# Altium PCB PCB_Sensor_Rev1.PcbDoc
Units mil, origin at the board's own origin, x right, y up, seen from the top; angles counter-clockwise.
Board outline 1760.04 x 1230.03 mil, 4 copper layers (Top Layer, Layer 1 (GND), Layer 2 (PWR), Bottom Layer), stack 61.456 mil thick; 69 components, 58 nets, 289 pads, 108 vias.
Unrouted connection lines stored in the file: 3.
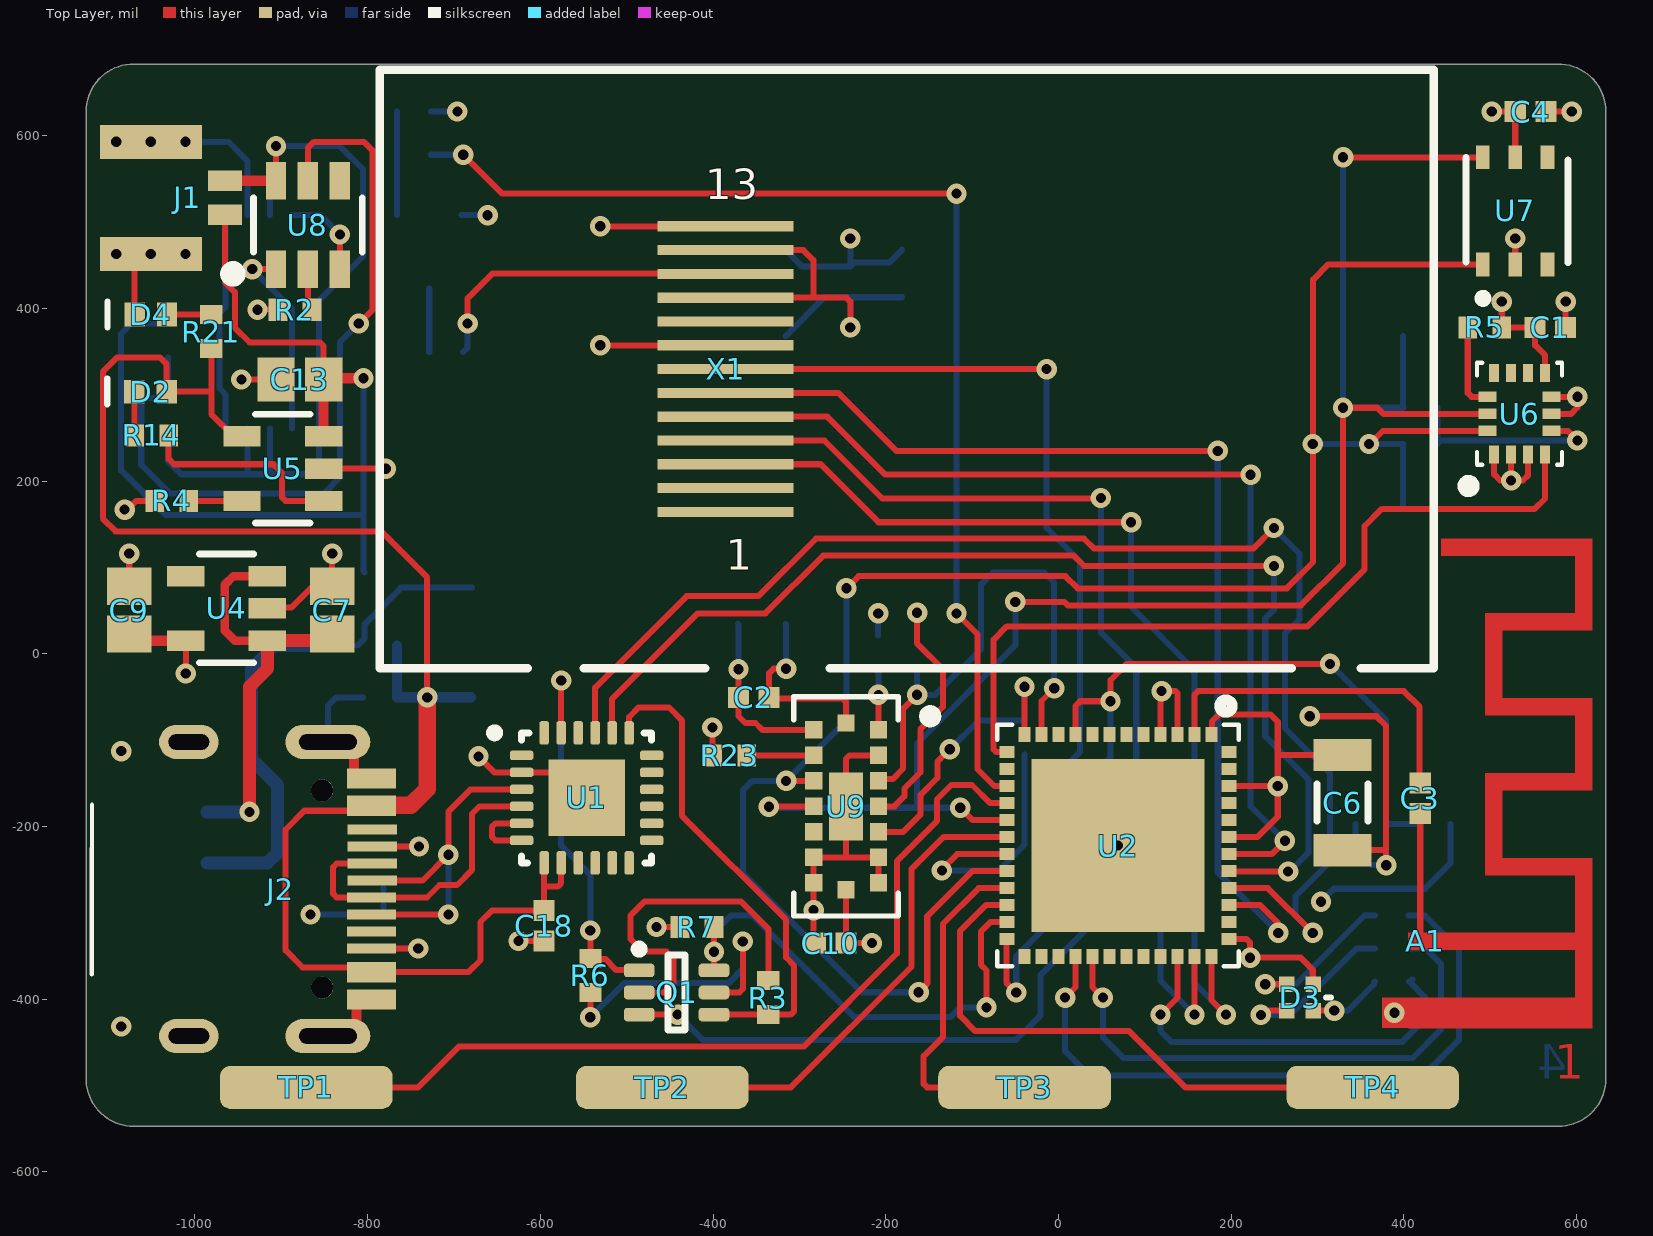
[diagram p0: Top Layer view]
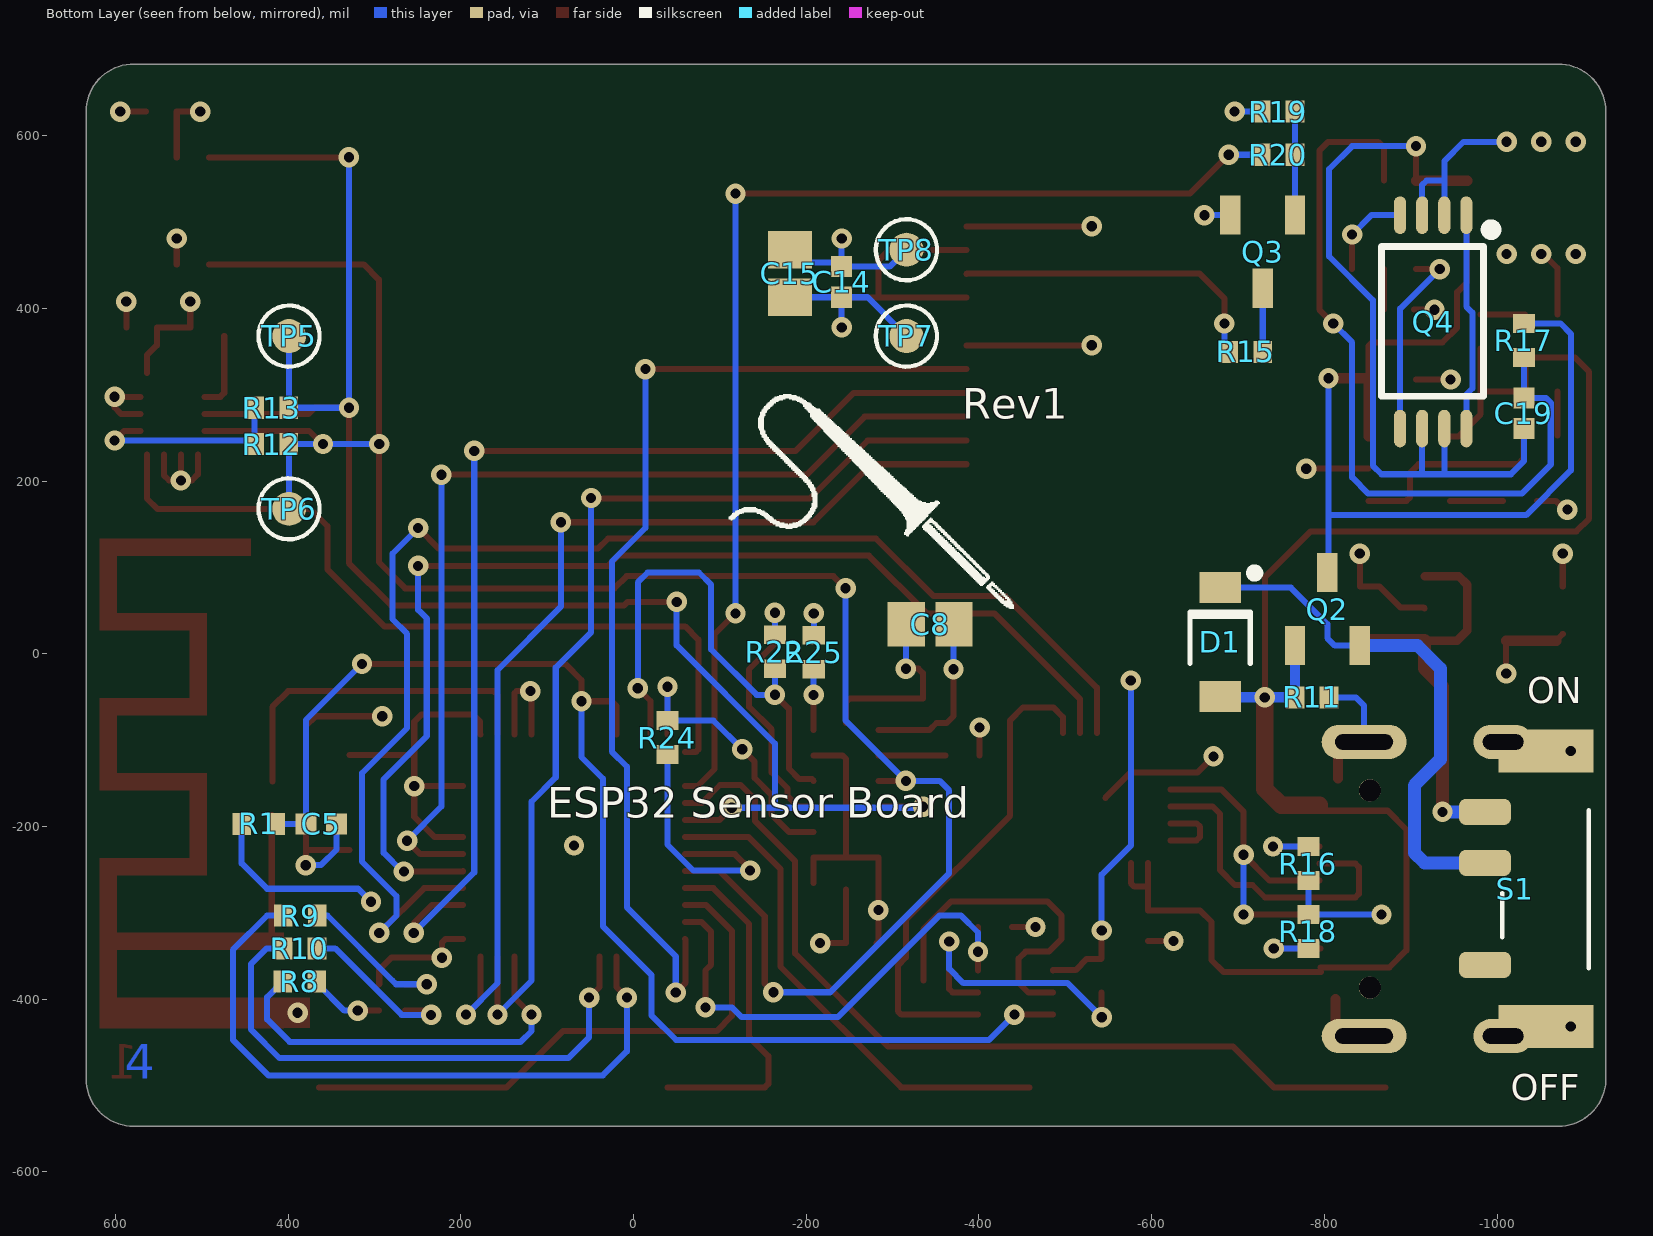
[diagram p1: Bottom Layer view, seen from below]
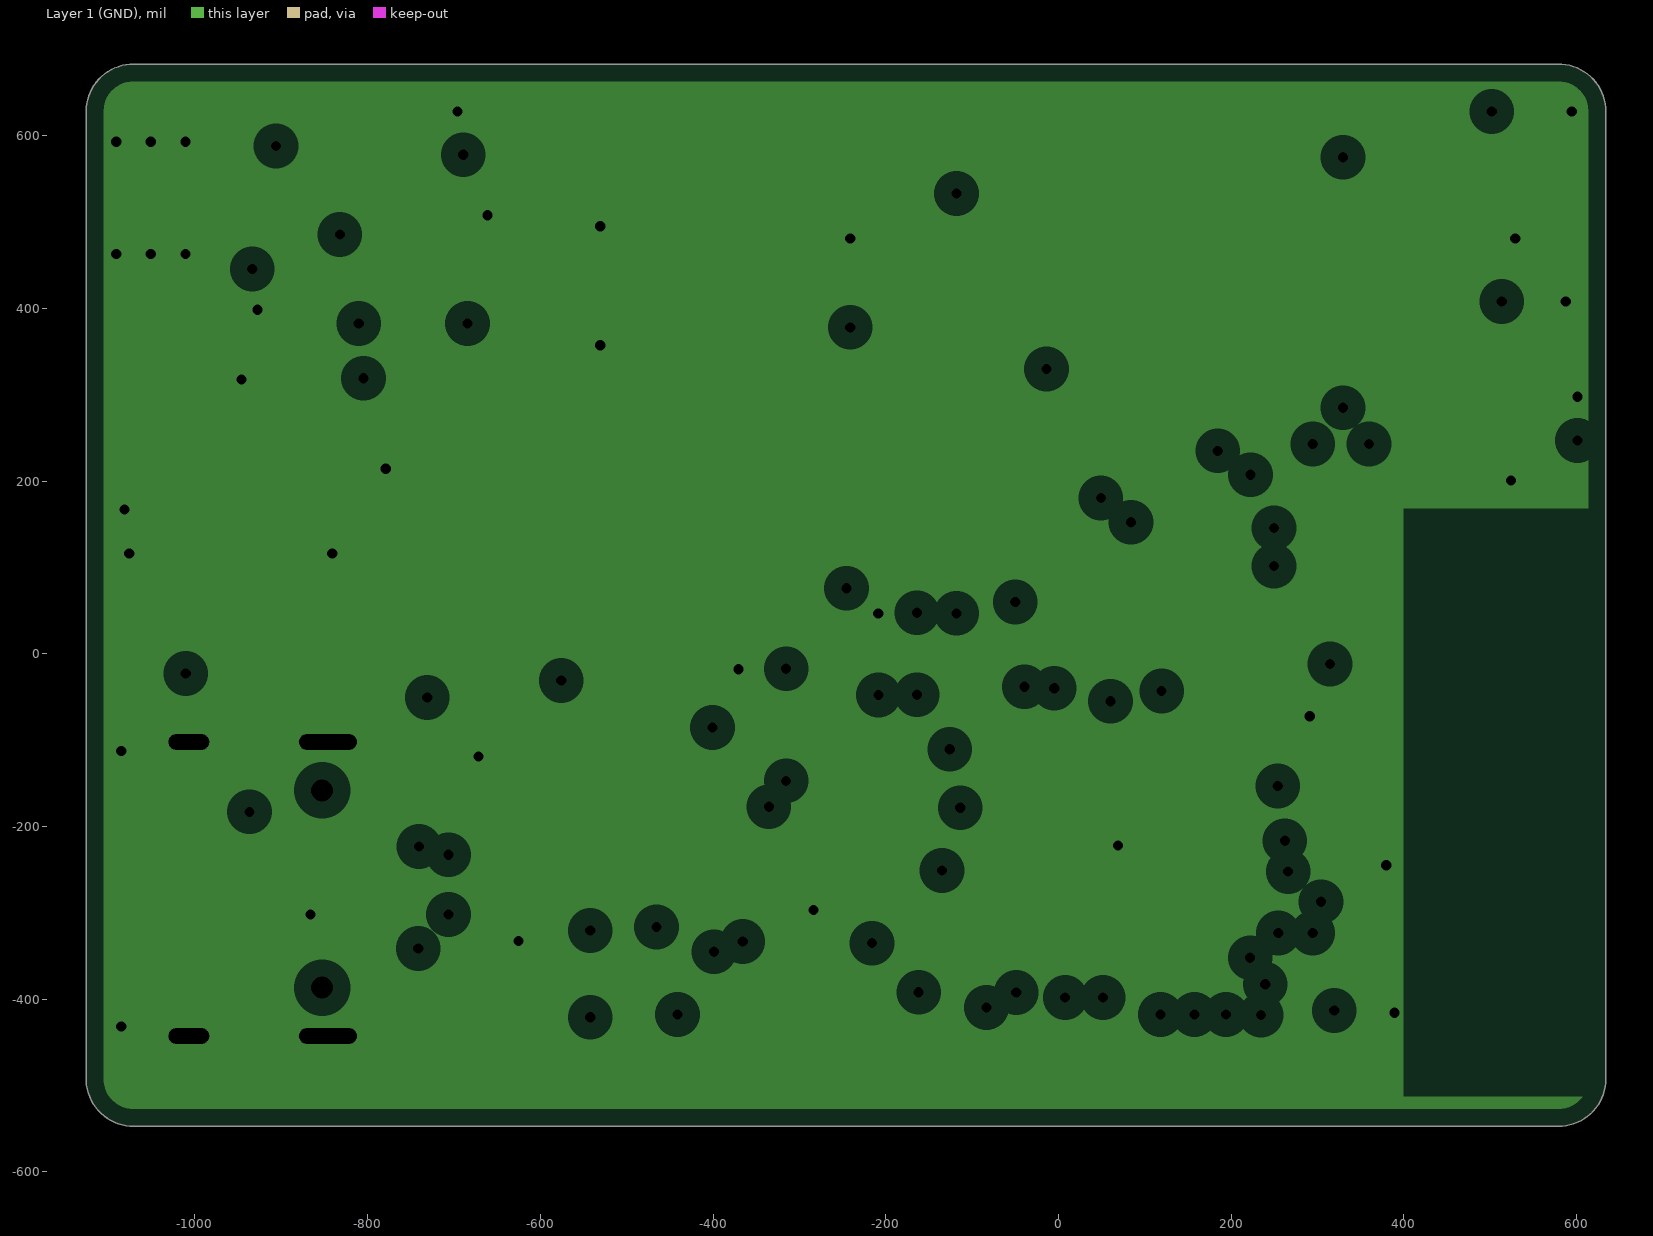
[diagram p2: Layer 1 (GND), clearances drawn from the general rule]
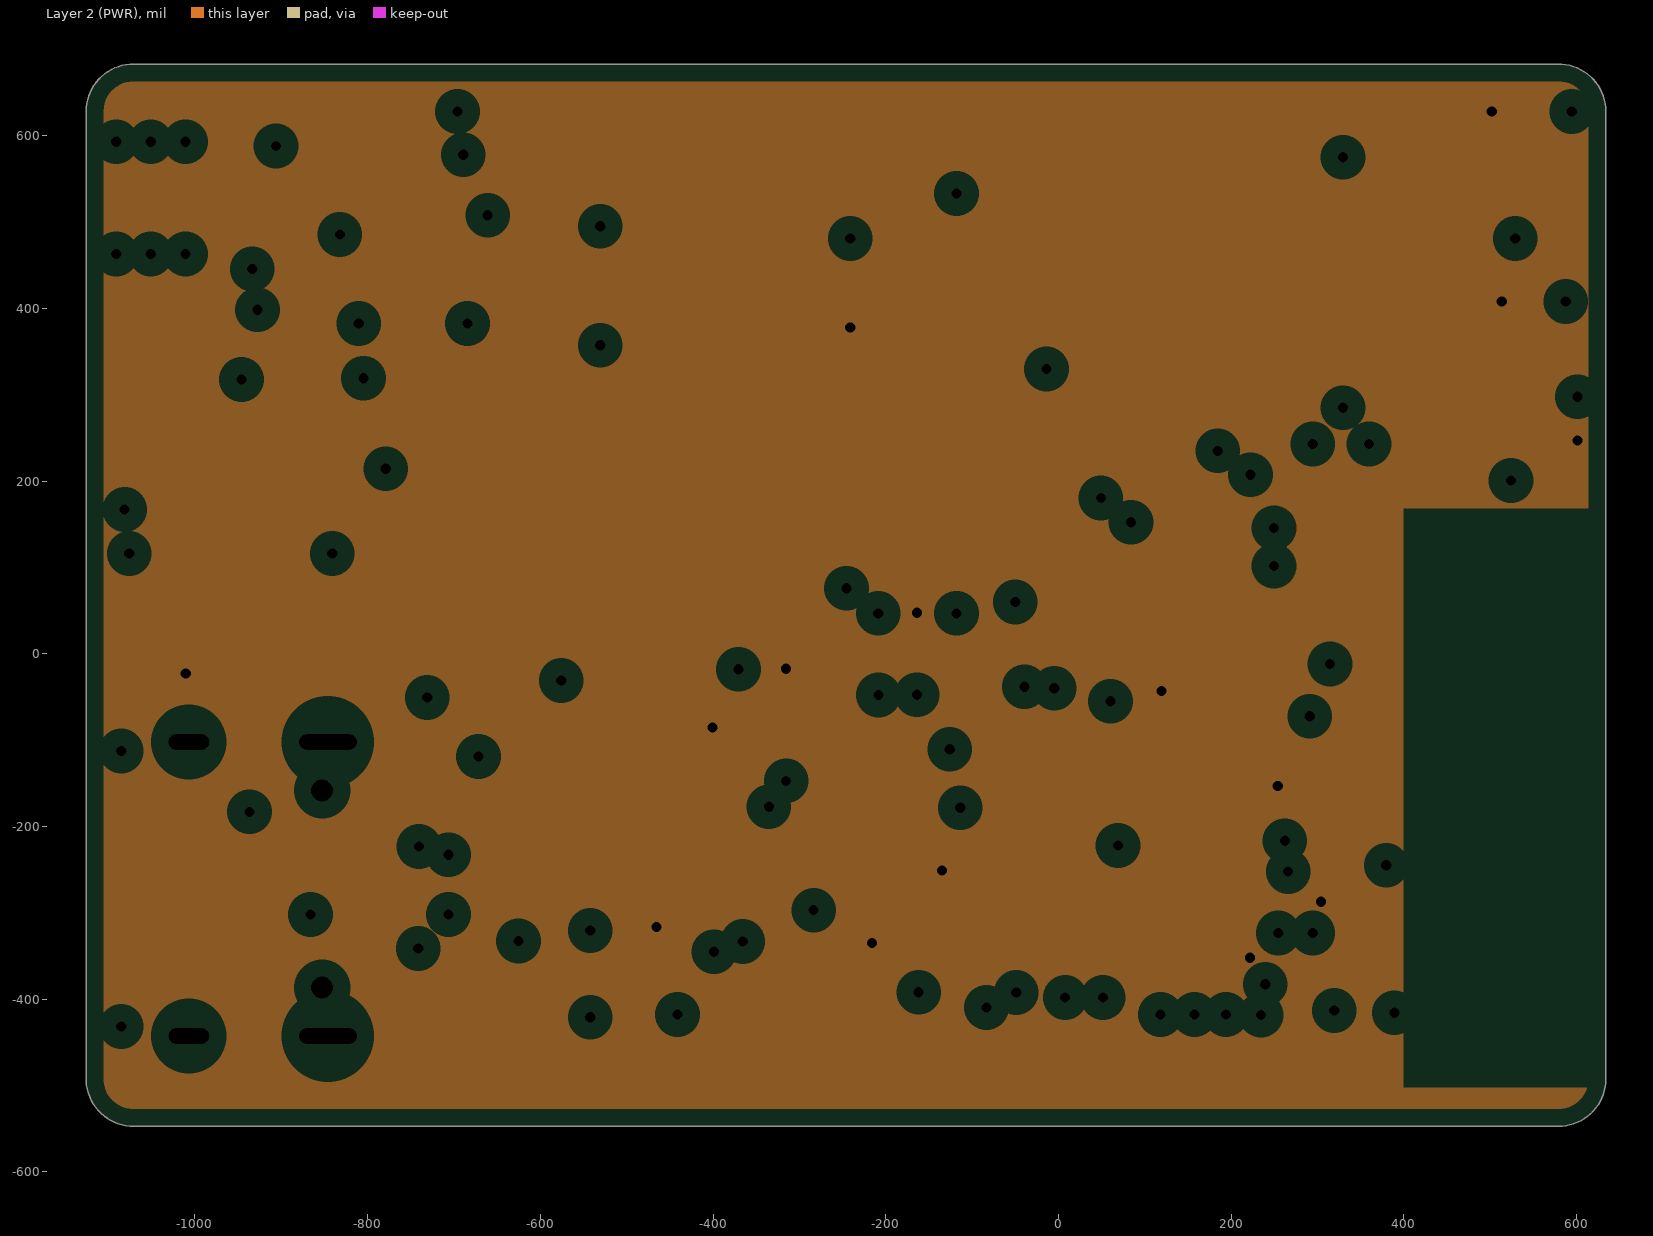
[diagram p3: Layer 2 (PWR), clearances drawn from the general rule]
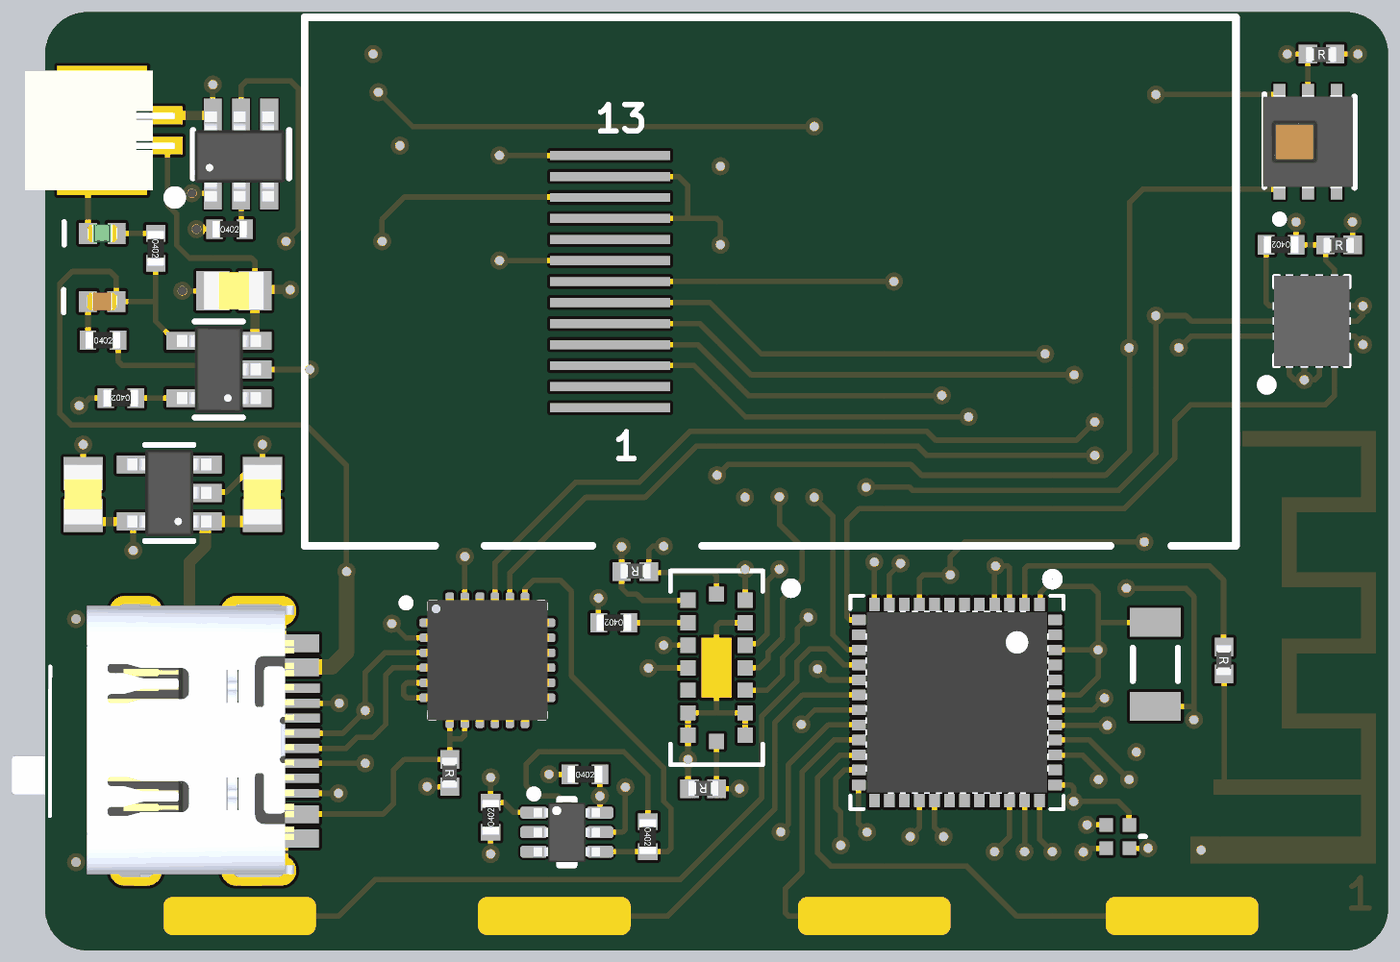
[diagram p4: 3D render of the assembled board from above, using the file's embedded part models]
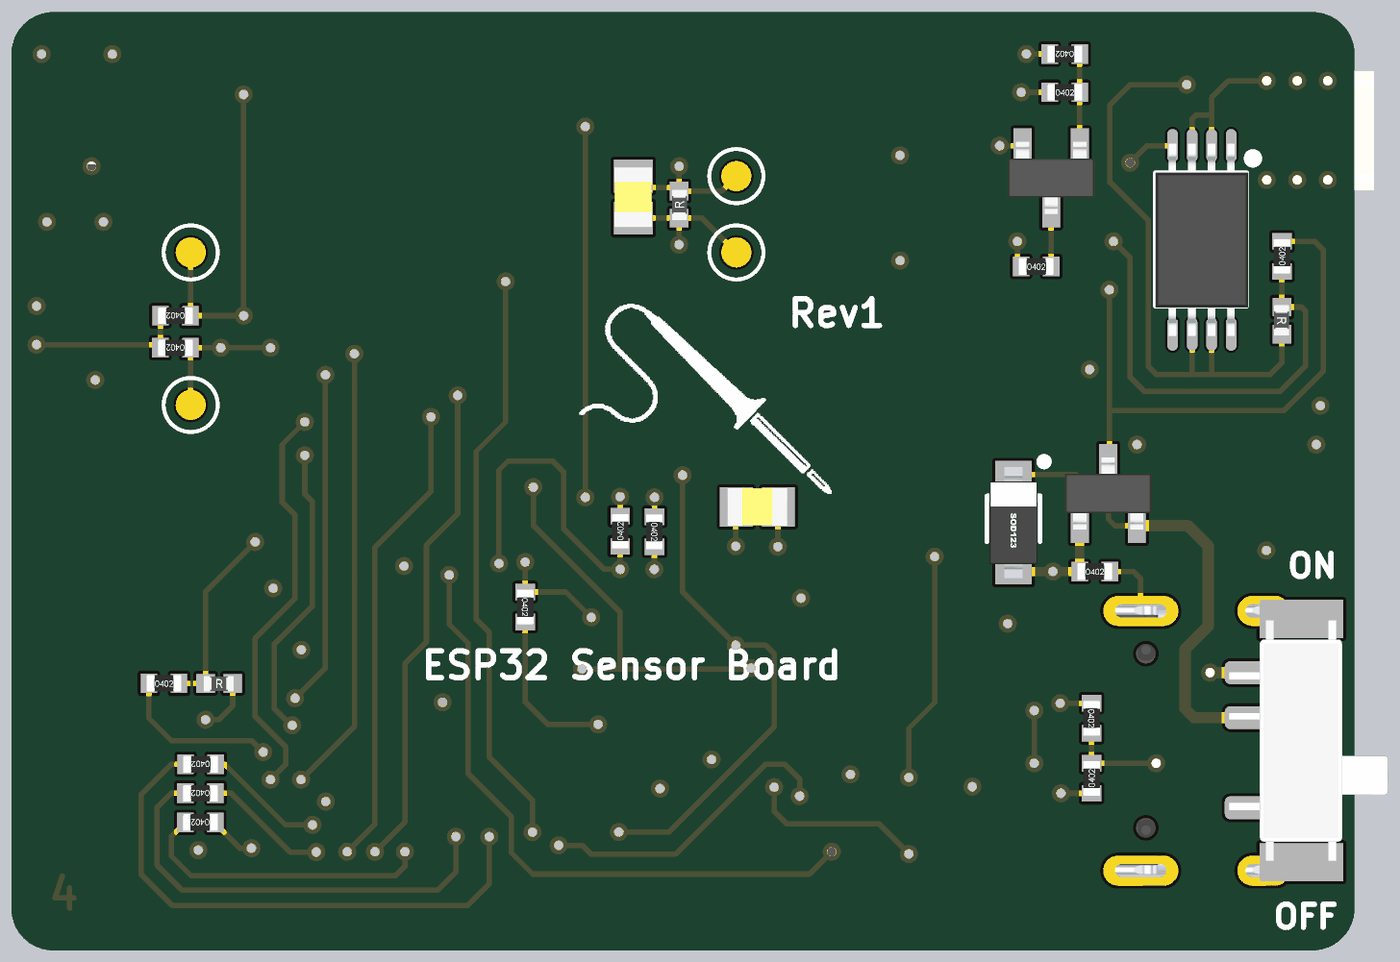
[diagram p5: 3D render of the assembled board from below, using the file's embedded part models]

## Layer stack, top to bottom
Top Solder: solder mask 0.4, Solder Resist, Dk 3.5
Top Layer: signal copper 1.4
Dielectric 2: prepreg 2.8, PP-006, Dk 4.1
Layer 1 (GND): plane copper 1.378, net GND
Dielectric 1: dielectric 50.3, FR-4, Dk 4.8
Layer 2 (PWR): plane copper 1.378, net +3.3V
Dielectric 3: prepreg 2.8, PP-006, Dk 4.1
Bottom Layer: signal copper 1.4
Bottom Solder: solder mask 0.4, Solder Resist, Dk 3.5

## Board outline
-1126.1,-497.17 -1126.1,-493.37 cw(c-1071.1,-492.17) -1126.12,-492.17 cw(c-1121.1,-492.17) -1126.1,-491.81 -1126.12,627.83 cw(c-1121.1,627.83) -1126.12,627.98 cw(c-1071.1,627.83) -1070.79,682.85 cw(c-1070.6,677.84) -1070.6,682.85 578.23,682.85 cw(c578.39,677.84) 578.34,682.85 cw(c578.89,627.84) 633.91,627.84 cw(c628.89,627.84) 633.9,627.7 633.92,-492.17 cw(c628.9,-492.17) 633.92,-492.17 cw(c628.9,-492.17) 633.92,-492.32 cw(c578.9,-492.17) 578.52,-547.18 cw(c578.4,-542.17) 578.4,-547.18 -1070.58,-547.18 ccw(c-1071.1,-492.17) -1070.55,-547.18 -1070.58,-547.18 cw(c-1071.1,-492.17) -1125.66,-499.23 cw(c-1121.09,-497.17)

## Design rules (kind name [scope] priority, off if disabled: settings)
Clearance Clearance_1 [All vs InComponent('U9')] p1: gap=5 ignorepadtopadclearanceinfootprint=FALSE
Clearance Clearance_J2 [InComponent('J2')] p2: gap=5 ignorepadtopadclearanceinfootprint=FALSE
Clearance Clearance_Q4 [InComponent('Q4')] p3: gap=9.2 ignorepadtopadclearanceinfootprint=FALSE
Clearance Clearance_U7 [All vs InComponent('U7')] p4: gap=7 ignorepadtopadclearanceinfootprint=FALSE
Clearance Clearance_H1 [All vs InComponent('H1')] p5: gap=9.5 ignorepadtopadclearanceinfootprint=FALSE
Clearance Clearance_U3 [All vs InComponent('U3')] p6: gap=9.5 ignorepadtopadclearanceinfootprint=FALSE
Clearance Clearance_Q1 [All vs InComponent('Q1')] p7: gap=9.5 ignorepadtopadclearanceinfootprint=FALSE
Clearance Clearance_X1 [All vs InComponent('X1')] p8: gap=8.5 ignorepadtopadclearanceinfootprint=FALSE
Clearance Clearance_U2 [All vs InComponent('U2')] p9: gap=5.8 ignorepadtopadclearanceinfootprint=FALSE
Clearance Clearance_U1 [All vs InComponent('U1')] p10: gap=7.8 ignorepadtopadclearanceinfootprint=FALSE
Clearance Clearance_U6 [All vs InComponent('U6')] p11: gap=7.5 ignorepadtopadclearanceinfootprint=FALSE
Clearance [All] p12: gap=10 ignorepadtopadclearanceinfootprint=FALSE except(0: Arc-Hole Track-Hole SMDPad-Hole THPad-Hole Via-Hole Fill-Hole Poly-Hole Region-Hole Text-Hole)
HoleSize [All] p1: absolutevalues=TRUE maxlimit=200 minlimit=1 maxpercent=80.000 minpercent=20.000
MinimumSolderMaskSliver MinimumSolderMaskSliver_U1 [All vs InComponent('U1')] p1: minsoldermaskwidth=0.5
MinimumSolderMaskSliver MinimumSolderMaskSliver_X1 [All vs InComponent('X1')] p2: minsoldermaskwidth=0.6
MinimumSolderMaskSliver [All] p3: minsoldermaskwidth=1
PlaneClearance [All] p1: clearance=20
PlaneConnect [All] p1: planeconnectstyle=Direct reliefexpansion=20 reliefentries=4 reliefconductorwidth=10 reliefairgap=10
PolygonConnect [All] p1: connectstyle=Relief reliefconductorwidth=10 reliefentries=4 polygonreliefangle="90 Angle" airgapwidth=10
RoutingVias [All] p1: holewidth=11.81 width=23.62 viastyle="Through Hole" minholewidth=11.81 minwidth=23.62 maxholewidth=11.81 maxwidth=23.62
SilkToSilkClearance [All] p1: silktosilkclearance=5
SilkToSolderMaskClearance [IsPad] p1: minsilkscreentomaskgap=5 clearancetoexposedcopper=TRUE
SolderMaskExpansion [All] p1: expansion=4 istentingtop=FALSE
Width [All] p1: maxlimit=40 minlimit=7 preferedwidth=7
24 further rules are at their usual default settings.

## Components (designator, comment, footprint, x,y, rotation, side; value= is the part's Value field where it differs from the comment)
A1 "Antenna_PCB" "ANTENNA PCB" 424.91,-333.17 r0 top locked value="PCB Antenna"
C1 "0.1uF" CAPC1005X56N 569.57,377.83 r0 top
C2 "0.1uF" CAPC1005X56N -352.83,-50.55 r180 top
C3 "1.5pF" CAPC1005X56N 418.91,-167.17 r270 top
C4 "0.1uF" CAPC1005X56N 546.61,627.84 r0 top
C5 "0.1uF" CAPC1005X56N 361.62,-197.17 r180 bottom
C6 "100uF" CAPC3216X160L 328.91,-172.28 r270 top
C7 "10uF" CAPC2012X140N -841.1,50.39 r90 top
C8 "4.7uF" CAPC2012X140N -343.65,34.2 r180 bottom
C9 "10uF" CAPC2012X140N -1076.1,50.39 r90 top
C10 "0.1uF" CAPC1005X56N -263.81,-335.13 r180 top
C13 "10uF" CAPC2012X140N -878.66,317.6 r180 top
C14 "0.1uF" CAPC1005X56N -241.1,430.55 r90 bottom
C15 "10uF" CAPC2012X140N -181.1,440.39 r90 bottom
C18 "1uF" CAPC1005X56N -595.63,-314.88 r270 top
C19 "0.1uF" CAPC1005X56N -1031.1,278.5 r270 bottom
D1 "MBR0520" SOD123 -679.32,13.51 r270 bottom
D2 "Red Led" LED1005X40N-Red -1051.47,303.46 r0 top locked
D3 "RGB" FC-B1010RGBT-HG 279.67,-398.01 r0 top value="RGB Led"
D4 "Green Led" LED1005X40N-Green -1051.1,392.83 r0 top locked
J1 "CON2" JST_Micro_2PIN -965.47,527.87 r270 top locked
J2 "USB-C" TYPE-C-31-M-12 -900.89,-272.44 r270 top locked
Q1 "BC847S" SOT65P210X110-6N -442.28,-393.27 r0 top value=2NPN
Q2 "FDN340P" SOT95P240X110-3N -803.49,51.77 r90 bottom value="Mosfet P-CH"
Q3 "MMBT3904-TP" SOT95P240X110-3N -728.69,465.52 r270 bottom
Q4 "FS8205A" "TSOP65P490X110-8N WIDE" -926.14,384.31 r270 bottom locked
R1 "10K" RESC1005X40L 434.02,-197.17 r180 bottom
R2 "1K" RESC1005X40L -884.28,398.37 r0 top
R3 "10K" RESC1005X40L -336.1,-398.19 r270 top
R4 "43K" RESC1005X40L -1026.8,176.93 r180 top
R5 "10K" RESC1005X40L 493.58,377.84 r180 top
R6 "10K" RESC1005X40L -542.16,-372.6 r90 top
R7 "10K" RESC1005X40L -418.66,-316.5 r0 top
R8 "1K" RESC1005X40L 386.36,-379.47 r0 bottom
R9 "1K" RESC1005X40L 385.91,-303.17 r0 bottom
R10 "1K" RESC1005X40L 386.23,-341.17 r0 bottom
R11 "100K" RESC1005X40L -785.77,-50.55 r180 bottom
R12 "2K" RESC1005X40L 419.03,242.83 r0 bottom
R13 "2K" RESC1005X40L 418.91,284.87 r0 bottom
R14 "4.7K" RESC1005X40L -1050.12,252.83 r0 top
R15 "22R" RESC1005X40L -709,349.45 r180 bottom
R16 "5.1K" RESC1005X40L -781.52,-242.91 r270 bottom
R17 "100R" RESC1005X40L -1031.1,362.7 r90 bottom
R18 "5.1K" RESC1005X40L -781.52,-321.65 r90 bottom
R19 "10K" RESC1005X40L -746.4,627.83 r0 bottom
R20 "1K" RESC1005X40L -746.4,577.83 r180 bottom
R21 "22K" RESC1005X40L -981.1,373.15 r270 top
R22 "47K" "RESC1005X40L (0402 FOOTPRINT)" -163.81,2.35 r90 bottom
R23 "47K" "RESC1005X40L (0402 FOOTPRINT)" -380.79,-117.68 r180 top
R24 "47K" "RESC1005X40L (0402 FOOTPRINT)" -39.37,-97.05 r270 bottom
R25 "47K" "RESC1005X40L (0402 FOOTPRINT)" -208.81,1.63 r270 bottom
S1 "SWITCH SLIDE" K3-1296S-E1 -1021.09,-272.17 r90 bottom
TP1 "Test Point, 1mm Top Layer" TP100TL#1 -819.04,-677.16 r90 top locked
TP2 "Test Point, 1mm Top Layer" TP100TL#2 -458.82,-502.17 r90 top locked
TP3 "Test Point, 1mm Top Layer" TP100TL#3 -541.1,-687.17 r90 top locked
TP4 "Test Point, 1mm Top Layer" TP100TL#4 -175.59,-663.27 r90 top locked
TP5 "Test Point, 1mm Top Layer" TP100TL#5 398.91,367.83 r180 bottom
TP6 "Test Point, 1mm Top Layer" TP100TL#5 398.91,167.83 r180 bottom
TP7 "Test Point, 1mm Top Layer" TP100TL#5 -316.09,367.83 r180 bottom
TP8 "Test Point, 1mm Top Layer" TP100TL#5 -316.09,467.83 r180 bottom
U1 "CP2104N" 24-QFN -546.42,-166.89 r0 top locked
U2 "ESP32-PICO-D4" QFN48_NEWEST 68.9,-222.17 r270 top locked
U4 "HT7833" SOT95P280X144-5N -963.35,52.52 r180 top
U5 "SL4054ST25P" SOT95P280X144-5N -898.35,214.33 r180 top
U6 "LSM6DS3" LSM6DS3 533.89,277.84 r90 top locked
U7 "HDC1080DMBT" HDC1080 528.89,512.84 r90 top
U8 "DW01A" SOT95P280X130-6N -869.22,496.65 r90 top locked
U9 "TOF Sensor" VL53L5CPV0GC/1 -246.09,-176.73 r0 top value=VL53L5CX
X1 "TFT_1.14\"" "TFT_GLASS 1.14 INCH" -385.59,329.65 r0 top

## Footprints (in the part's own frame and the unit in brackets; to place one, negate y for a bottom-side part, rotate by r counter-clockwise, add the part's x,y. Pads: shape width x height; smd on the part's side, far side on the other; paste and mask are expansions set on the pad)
24-QFN [mm] "24-QFN Exposed Pad (4x4)"
  rrect50% 0.69x0.28 smd: 1(-1.912,1.25) 2(-1.912,0.75) 3(-1.912,0.25) 4(-1.912,-0.25) 5(-1.912,-0.75) 6(-1.912,-1.25) 13(1.913,-1.25) 14(1.913,-0.75) 15(1.913,-0.25) 16(1.913,0.25) 17(1.913,0.75) 18(1.913,1.25)
  rrect50% 0.28x0.69 smd: 7(-1.25,-1.913) 8(-0.75,-1.913) 9(-0.25,-1.913) 10(0.25,-1.913) 11(0.75,-1.913) 12(1.25,-1.913) 19(1.25,1.913) 20(0.75,1.913) 21(0.25,1.913) 22(-0.25,1.913) 23(-0.75,1.913) 24(-1.25,1.913)
  rect 2.25x2.25 smd paste-1.3: 25(0,0)
  silkscreen extent -2.83,-1.91 1.91,2.04, body extent -2.05,-2.04 2.05,2.06, height 1.08
"ANTENNA PCB" [mil] "PCB Antenna Wifi/Bluetooth"
  Top Layer region: -19.69,-9.84 173.23,-9.84 173.23,-64.96 -19.69,-64.96 -19.69,-100.39 192.91,-100.39 192.91,96.46 88.98,96.46 88.98,175.2 192.91,175.2 192.91,281.5 88.98,281.5 88.98,360.24 192.91,360.24 192.91,466.54 18.11,466.54 18.11,446.85 173.23,446.85 173.23,379.92 69.29,379.92 69.29,261.81 173.23,261.81 173.23,194.88 69.29,194.88 69.29,76.77 173.23,76.77 173.23,9.84 -19.69,9.84 -19.69,-9.84
CAPC1005X56N [mm] "Chip Capacitor, 2-Leads, Body 1.0x0.5mm, IPC Medium Density (0402 ceramic)"
  rect 0.62x0.62 smd: 1(-0.45,0) 2(0.45,0)
  body extent -0.55,-0.3 0.55,0.3, height 0.6
CAPC2012X140N [mm] "Chip Capacitor, 2-Leads, Body 2.0x1.3mm, IPC Medium Density (0805 ceramic)"
  rect 1.1x1.3 smd: 1(-0.7,0) 2(0.7,0)
  body extent -1,-0.62 1,0.63, height 1.24
CAPC3216X160L [mm] "Chip Capacitor, 2-Leads, Body 3.2x1.6mm, IPC Least Density(C1206)"
  rect 0.95x1.7 smd: 1(-1.4,0) 2(1.4,0)
  silkscreen extent -0.55,-0.75 0.55,0.75, body extent -1.7,-0.9 1.7,0.9, height 1.9
FC-B1010RGBT-HG [mm] "LED,RGB,SMD,RoHS"
  rect 0.45x0.45 smd: 1(0.387,0.388) 2(0.387,-0.387) 3(-0.387,-0.387) 4(-0.387,0.388)
  silkscreen extent 0.76,0 0.91,0, body extent -0.53,-0.55 0.53,0.58, height 0.9
HDC1080 [mm] "Temp/Humidity Sensor"
  rect 0.7x0.4 smd mask+0.076: 1(-1.575,0.95) 2(-1.575,0) 3(-1.575,-0.95) 4(1.575,-0.95) 5(1.575,0) 6(1.575,0.95)
  silkscreen extent -2.7,-1.55 1.57,1.45, body extent -1.55,-1.5 1.55,1.5, height 0.85
JST_Micro_2PIN [mm]
  rect 0.6x1 smd paste-0.508: 1(0.5,0) 2(-0.5,0)
  rect 1x3 smd paste-1.27: ""(-1.65,-2.175) ""(1.65,-2.175)
  body extent -1.99,-4.74 2,0.24, height 2.9
K3-1296S-E1 [mil] "Toggle Switches SMD RoHS"
  rrect50% 30x60 smd: 1(89.06,35) 2(30,35) 3(-88.11,35)
  rect 50x110 smd: 4(-159.45,-35.43) 4(159.45,-35.43)
  silkscreen extent -92,-85 91,15, body extent -157,-149 158,59, height 60
LED1005X40N-Green [mm] "Chip LED 2-Leads, Body 1.0x0.5mm, (0402)"
  rect 0.6x0.7 smd: 1(-0.475,0) 2(0.475,0)
  body extent -0.5,-0.3 0.5,0.3, height 0.2
LED1005X40N-Red [mm] "Chip LED 2-Leads, Body 1.0x0.5mm, (0402)"
  rect 0.6x0.7 smd: 1(-0.475,0) 2(0.475,0)
  body extent -0.5,-0.3 0.5,0.3, height 0.2
LSM6DS3 [mm] "IMU ACCEL/GYRO I2C/SPI 14VFLGA"
  rect 0.525x0.3 smd mask+0.076: 1(-1.2,0.75) 2(-1.2,0.25) 3(-1.2,-0.25) 4(-1.2,-0.75) 8(1.2,-0.75) 9(1.2,-0.25) 10(1.2,0.25) 11(1.2,0.75)
  rect 0.3x0.525 smd mask+0.076: 5(-0.5,-0.94) 6(0,-0.94) 7(0.5,-0.94) 12(0.5,0.94) 13(0,0.94) 14(-0.5,0.94)
  silkscreen extent -2.32,-1.25 1.5,1.7, body extent -1.55,-1.3 1.55,1.3, height 0.86
QFN48_NEWEST [mm] "QFN, 48-Leads, Body 7x7mm, Pitch 0.5mm, IPC Medium Density"
  rrect9% 0.45x0.35 smd: 1(-3.265,2.75) 2(-3.265,2.25) 3(-3.265,1.75) 4(-3.265,1.25) 5(-3.265,0.75) 6(-3.265,0.25) 7(-3.265,-0.25) 8(-3.265,-0.75) 9(-3.265,-1.25) 10(-3.265,-1.75) 11(-3.265,-2.25) 12(-3.265,-2.75) 25(3.265,-2.75) 26(3.265,-2.25) 27(3.265,-1.75) 28(3.265,-1.25) 29(3.265,-0.75) 30(3.265,-0.25) 31(3.265,0.25) 32(3.265,0.75) 33(3.265,1.25) 34(3.265,1.75) 35(3.265,2.25) 36(3.265,2.75)
  rrect9% 0.35x0.45 smd: 13(-2.75,-3.265) 14(-2.25,-3.265) 15(-1.75,-3.265) 16(-1.25,-3.265) 17(-0.75,-3.265) 18(-0.25,-3.265) 19(0.25,-3.265) 20(0.75,-3.265) 21(1.25,-3.265) 22(1.75,-3.265) 23(2.25,-3.265) 24(2.75,-3.265) 37(2.75,3.265) 38(2.25,3.265) 39(1.75,3.265) 40(1.25,3.265) 41(0.75,3.265) 42(0.25,3.265) 43(-0.25,3.265) 44(-0.75,3.265) 45(-1.25,3.265) 46(-1.75,3.265) 47(-2.25,3.265) 48(-2.75,3.265)
  rect 5.08x5.08 smd paste-0.762: 49(0,0)
  silkscreen extent -4.28,-3.55 3.55,3.55, body extent -3.05,-3.05 3.05,3.05, height 0.9
RESC1005X40L [mm] "Chip Resistor, 2-Leads, Body 1.0x0.5mm, IPC Medium Density (0402)"
  rect 0.55x0.65 smd: 1(-0.5,0) 2(0.5,0)
  body extent -0.57,-0.27 0.58,0.28, height 0.41
"RESC1005X40L (0402 FOOTPRINT)" [mm] "Chip Resistor, 2-Leads, Body 1.0x0.5mm, IPC Medium Density (0402)"
  rect 0.55x0.65 smd: 1(-0.5,0) 2(0.5,0)
  body extent -0.57,-0.27 0.58,0.28, height 0.41
SOD123 [mil] "Molded Diode, 2-Leads, Body 2.85x1.8mm, IPC Medium Density (SOD123)"
  rect 36x48 smd: 1(-63,0) 2(63,0)
  silkscreen extent -85,-35 25,45, body extent -73,-31 73,32, height 50
SOT65P210X110-6N [mm] "SC70, 6-Leads, Body 2.4x2.2mm (max), Pitch 0.65mm, IPC Medium Density"
  rrect50% 0.9x0.4 smd mask+0.076: 1(-1.1,0.675) 2(-1.1,0.025) 3(-1.1,-0.625) 4(1.1,-0.625) 5(1.1,0.025) 6(1.1,0.675)
  silkscreen extent -1.22,-1.07 0.25,1.42, body extent -1.1,-0.97 1.1,1.01, height 0.99
SOT95P240X110-3N [mm] "SOT23, 3-Leads, Body 3.0x2.5mm (max), Pitch 0.95mm, IPC Medium Density"
  rect 1.15x0.6 smd: 1(-1.075,0.95) 2(-1.075,-0.95) 3(1.075,0)
  body extent -1.2,-1.45 1.2,1.45, height 0.99
SOT95P280X130-6N [mm] "SOT23, 6-Leads, Body 3.0x3.0mm (max), Pitch 0.95mm, IPC Medium Density"
  rect 1.1x0.6 smd mask+0.051: 1(-1.3,0.94) 2(-1.3,0) 3(-1.3,-0.94) 4(1.3,-0.94) 5(1.3,0) 6(1.3,0.94)
  silkscreen extent -1.57,-1.6 0.8,2.33, body extent -1.57,-1.45 1.43,1.55, height 1.45
SOT95P280X144-5N [mm] "SOT23, 5-Leads, Body 3.1x3.0mm (max), Pitch 0.95mm, IPC Medium Density (RFMD SOT23-5)"
  rect 1.1x0.6 smd: 1(-1.2,0.95) 2(-1.2,0) 3(-1.2,-0.95) 4(1.2,-0.95) 5(1.2,0.95)
  silkscreen extent -0.8,-1.6 0.8,1.6, body extent -1.4,-1.45 1.4,1.45, height 1.45
"TFT_GLASS 1.14 INCH" [mm] "TFT_GLASS 0.14 INCH"
  rect 4x0.3 smd: 1(0,-4.2) 2(0,-3.5) 3(0,-2.8) 4(0,-2.1) 5(0,-1.4) 6(0,-0.7) 7(0,0) 8(0,0.7) 9(0,1.4) 10(0,2.1) 11(0,2.8) 12(0,3.5) 13(0,4.2)
  silkscreen extent -10.17,-8.8 20.83,8.8, body extent -10.17,-8.8 20.83,8.8, height 2
TP100TL#1 [mil] "Test Point"
  rrect50% 50x200 smd paste-80 mask+0: 1(175,52.06)
TP100TL#2 [mil] "Test Point"
  rrect50% 50x200 smd paste-80 mask+0: 1(0,0)
TP100TL#3 [mil] "Test Point"
  rrect50% 50x200 smd paste-80 mask+0: 1(185,-501.73)
TP100TL#4 [mil] "Test Point"
  rrect50% 50x200 smd paste-80 mask+0: 1(161.1,-539.49)
TP100TL#5 [mil] "Test Point"
  round 39.37 smd paste-19.68 mask+3: 1(0,0)
  silkscreen extent -35,-35 35,35
"TSOP65P490X110-8N WIDE" [mil] "TSOP, Wide, 8-Leads, Body 464x3.0mm (max), Pitch 0.65mm, IPC Medium Density"
  oval 43.5x14 smd mask+3: 1(-123.52,38.39) 2(-123.52,12.8) 3(-123.52,-12.8) 4(-123.52,-38.39) 5(123.52,-38.39) 6(123.52,-12.8) 7(123.52,12.8) 8(123.52,38.39)
  silkscreen extent -113,-60 86,73, body extent -126,-61 126,61, height 43
TYPE-C-31-M-12 [mm] "USB-C Connector"
  oval 1x2.5 hole 0.45 slot 1.7 at 90 deg: 1(-4.325,1.392) 1(4.325,1.392)
  oval 1x1.75 hole 0.45 slot 1.2 at 90 deg: 1(-4.325,-2.698) 1(4.325,-2.698)
  rect 0.3x1.45 smd: A1(-3.401,2.675) A4(-2.601,2.673) A5(-1.25,2.698) A6(-0.25,2.698) A7(0.25,2.673) A8(1.25,2.673) A9(2.598,2.673) A12(3.401,2.673) B1(3.101,2.673) B4(2.304,2.673) B5(1.75,2.673) B6(0.75,2.673) B7(-0.75,2.698) B8(-1.75,2.698) B9(-2.301,2.673) B12(-3.101,2.675)
  round 0.65 hole 0.65 unplated: ""(-2.9,1.223) ""(2.9,1.223)
  silkscreen extent -2.47,-5.56 2.51,-5.55, body extent -4.5,-4.33 4.44,2.57, height 3.31
VL53L5CPV0GC/1 [mil] "IC,LASER SENSOR,17pin"
  rect 20x20 smd: A1(37.5,88.58) A2(37.5,59.06) A3(37.5,29.53) A4(37.5,0) A5(37.5,-29.53) A6(37.5,-59.06) A7(37.5,-88.58) B1(0,96.5) B7(0,-96.5) C1(-37.5,88.58) C2(-37.5,59.06) C3(-37.5,29.53) C4(-37.5,0) C5(-37.5,-29.53) C6(-37.5,-59.06) C7(-37.5,-88.58)
  rect 39.37x78.74 smd paste-78.74: B4(0,0)
  silkscreen extent -60,-127 105,127, body extent -60,-127 60,127, height 59

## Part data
A1: "Antenna PCB 2.4G"
C1 C2 C4 C5 C10 C14 C19: library part CAP_0402, "CAP 0.1uF 0402", Manufacturer=CCTC, PartNumber=C344190
C3: library part CAP_0402, "CAP 1.5pF 0402", Manufacturer=Dafron
C6: library part CAP_1206, "CAP 100uF 6.3V 1206", Manufacturer="Taiyo Yuden", PartNumber=C87164
C7 C9 C13 C15: library part CAP_0805, "CAP 10uF 0805", Manufacturer=Samsung, PartNumber=C307520
C8: library part CAP_0805, "CAP 4.7uF 0805"
C18: library part CAP_0603, "CAP 1uF 16V 0402", Manufacturer=Walsin, PartNumber=C83063
D1: library part MBR0520-TP, "DIODE SCHOTTKY 20V 500MA SOD123", Manufacturer=CJ, PartNumber=C475717
D2: library part LED_0402_SMALL_Red, "LED RED 0603"
D3: library part FC-B1010RGBT-HG, "LED,RGB LED,SMD,RoHS", Manufacturer=Foshan, PartNumber=C158099
D4: library part LED_0402_SMALL_GREEN, "LED Green 0402"
J1: library part JST_Micro_CONN_2PIN, "JST MIcro CONN 2POS"
J2: "CONN RECPT USB-C", Manufacturer=KHE
Q1: "TRANS 2NPN 44V 0.1A SC-70-6", Manufacturer=Changjiang
Q2: "MOSFET P-CH 20V 2A SOT-23", Manufacturer="On Semi"
Q3: "TRANSISTOR NPN SOT23", Manufacturer="Micro Commercial", PartNumber=C668969
Q4: "MOSFET 2N-CH 20V 6A TSSOP-8L", Manufacturer=Fortune, PartNumber=C16052
R1 R3 R5 R6 R7 R19: library part RES_0402, "RES 10K 0402", Manufacturer=Guangdong, PartNumber=C258091
R2 R8 R9 R10 R20: library part RES_0402, "RES 1K 0402", Manufacturer=Yageo, PartNumber=C106235
R4: library part RES_0603, "RES 43K 0402", Manufacturer=Uniroyal, PartNumber=C8329
R11: library part RES_0603, "RES 100K 0402", Manufacturer="Uniroyal Elec", PartNumber=C25741
R12 R13: library part RES_0402, "RES 2K 0402", Manufacturer="LIZ Elec", PartNumber=C100291
R14: library part RES_0603, "RES 4.7K 0402", Manufacturer="LIZ Elec", PartNumber=C100139
R15: library part RES_0402, "RES 22R 0402", Manufacturer=Uniroyal, PartNumber=C25092
R16 R18: library part RES_0603, "RES 5.1K 0402"
R17: library part RES_0603, "RES 100R 0402", Manufacturer=Yageo, PartNumber=C106232
R21: library part RES_0603, "RES 22K 0402", Manufacturer="LIZ Elec", PartNumber=C100310
R22 R23 R24 R25: library part RES_0402, "RES 47K 0402"
S1: library part K3-1296S-E1, "SWITCH SLIDE SMD", Manufacturer="Korean Hroparts Elec", PartNumber=C128955
TP1 TP2 TP3 TP4 TP5 TP6 TP7 TP8: Manufacturer=N/A
U1: "IC BRIDGE USB TO UART 24QFN", Manufacturer="Silicon Labs", PartNumber=C47742
U2: "RF Transceiver ICs QFN-48_7x7x05P RoHS", Manufacturer=Espressif, PartNumber=C193707
U4: "IC LDO 3.3V 0.5A SOT23-5", Manufacturer=Holtek, PartNumber=C164106
U5: "Charger IC Lithium-Ion/Polymer SOT23-5", Manufacturer=Techfuse, PartNumber=C258510
U6: library part "LSM6DS3 (obsolete)", "IMU ACCEL/GYRO I2C/SPI 14VFLGA", Manufacturer="ST MICRO"
U7: "Humidity/Temperature Sensor", Manufacturer="Texas Instruments", PartNumber=C82227
U8: "IC LITHIUM BATT PROTECT SOT-23-6L", Manufacturer=PUOLOP, PartNumber=C351410
U9: library part VL53L5CXV0GC/1, "IC,LASER SENSOR,17pin", Manufacturer="ST MICRO"
X1: library part "TFT_GLASS 1.14 INCH COLOR", "1.14 INCH TFT GLASS COLOR", Manufacturer=BuyDisplay

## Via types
v1: diameter 23.62, hole 11.81, Top Layer to Bottom Layer, tented both sides, 108 vias

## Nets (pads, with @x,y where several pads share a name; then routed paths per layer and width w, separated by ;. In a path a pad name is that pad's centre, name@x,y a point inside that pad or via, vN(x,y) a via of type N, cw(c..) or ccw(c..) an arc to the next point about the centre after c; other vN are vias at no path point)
+3.3V: C1.1 C2.1 C4.1 C6.1 C8.1 C9.1 C10.1 C14.1 C15.1 D3.1 R1.1 R5.1 R7.1 R12.2 R13.2 R22.2 R23.2 R24.2 TP7.1 U2.1 U2.3 U2.4 U2.19 U2.37 U2.43 U2.46 U4.5 U6.5 U6.8 U7.5 U9.A4 U9.B1 U9.B7 X1.10 X1.12 | length 2915.4
  Top Layer w7: C9.1 C9.1@-1068.39,15.12 ; v1(-1010.59,-22.88) U4.5 ; v1(-465.59,-316.5) R7.1 ; v1(-400.81,-85.37) -400.81,-117.34 R23.2 ; X1.10 -283.81,412.32 ; X1.12 -295.59,467.44 -283.81,455.66 -283.81,412.32 ; C2.1@-335.12,-51.67 -250.54,-51.67 -246.09,-56.12 U9.B1 ; C2.1 -335.12,-22.45 -330,-17.34 v1(-315.43,-17.34) ; U9.B7 C10.1 v1(-216.09,-335.13) ; v1(-241.1,377.95) -241.1,407.83 -245.59,412.32 -283.81,412.32 ; U9.A4 -190.21,-176.73 -178.51,-165.03 -178.51,-156.07 -160,-137.56 -160,-87.69 -133.81,-61.49 -133.81,-18.2 -163.81,11.8 v1(-163.81,47.47) ; v1(-135,-251) -135,-249.52 -117.49,-232.01 U2.19 ; U2.4 118.11,-43.27 v1(119.41,-43.27) 135.51,-43.27 137.8,-45.55 U2.3 ; U2.1 177.71,-93.08 177.71,-78.36 185.91,-70.17 245.29,-70.17 253.9,-78.78 v1(253.9,-153.27) ; U2.37 217.81,-330.43 221.91,-334.53 v1(221.91,-352.17) 222.44,-351.64 279.93,-351.64 294.41,-366.11 294.41,-382.24 D3.1 ; U2.43 230.35,-212.32 253.9,-188.78 v1(253.9,-153.27) ; U2.46 v1(253.9,-153.27) ; 253.9,-117.17 C6.1 ; v1(501.68,627.84) C4.1 U7.5 ; v1(513.27,407.83) R5.1 C1.1 551.85,357.2 563.42,345.64 U6.8 ; U6.5 589.7,258.16 v1(600.89,246.97)
  Top Layer w12: C9.1@-1068.39,15.12 U4.5
  Bottom Layer w7: C8.1 -315.43,33.55 v1(-315.43,-17.34) ; TP7.1 -271.09,412.83 C14.1 ; v1(-241.1,377.95) C14.1 ; C15.1 C14.1 ; R22.2 v1(-163.81,47.47) ; v1(-135,-251) -69.37,-251 -39.37,-221 R24.2 ; v1(303.91,-287.17) 318.91,-272.17 424.34,-272.17 453.7,-242.81 R1.1 ; R13.2@438.71,284.87 R12.2 442.85,246.97 v1(600.89,246.97)
BLUE: R9.2 U2.28 | length 778.5
  Top Layer w7: v1(7.68,-398.19) 19.68,-386.18 U2.28
  Bottom Layer w7: v1(7.68,-398.19) 7.68,-460.43 35.51,-488.27 422.85,-488.27 463.91,-447.2 463.91,-342.91 424.17,-303.17 R9.2
D+: J2.A6 J2.B6 U1.3 | length 404.3
  Top Layer w7: J2.B6 v1(-706.52,-301.97) ; J2.A6 -736.32,-262.6 v1(-706.52,-232.8) -706.52,-182.76 -680.81,-157.05 U1.3
  Bottom Layer w7: v1(-706.52,-301.97) v1(-706.52,-232.8)
D-: J2.A7 J2.B7 U1.4 | length 379.9
  Top Layer w7: -840.11,-247.36 -840.11,-278.18 -836.01,-282.28 J2.A7 -731.34,-282.28 -716.85,-267.8 -696.45,-267.8 -679.32,-250.67 -679.32,-185.55 -670.5,-176.73 U1.4 ; -840.11,-247.01 -836.01,-242.91 J2.B7
DC: U2.42 X1.5 | length 1147.3
  Top Layer w7: X1.5 -267.76,274.53 -200.59,207.36 v1(222.41,207.36) ; U2.42 246.69,-232.01 v1(262.13,-216.57)
  Bottom Layer w7: v1(222.41,207.36) 222.41,-176.86 v1(262.13,-216.57)
DTR: Q1.1 R6.2 U1.23 | length 458.9
  Top Layer w7: U1.23 v1(-575.95,-30.96) ; v1(-542.16,-320.47) R6.2 -541.65,-353.42 -524.84,-353.42 -511.92,-366.35 -485.93,-366.35 Q1.1
  Bottom Layer w7: v1(-575.95,-30.96) -575.95,-222.17 -542.16,-255.95 v1(-542.16,-320.47)
EN: C5.1 Q1.3 R1.2 U2.9 | length 1495.7
  Top Layer w7: Q1.3 v1(-441.1,-417.87) ; U2.9 19.68,-60.38 25.06,-55 v1(60.16,-55) 60.16,-30.71 79.1,-11.77 v1(314.41,-11.77)
  Bottom Layer w7: v1(-441.1,-417.87) -411.77,-447.2 -49.2,-447.2 -21.11,-419.11 -21.11,-372.18 35.51,-315.56 35.51,-144.49 60.16,-119.84 v1(60.16,-55) ; v1(314.41,-11.77) 379.33,-76.7 C5.1 R1.2
GND: C1.2 C2.2 C4.2 C5.2 C6.2 C7.2 C8.2 C9.2 C10.2 C13.2 C14.2 C15.2 C18.2 D4.1 J1. J2.1 J2.A1 J2.A12 J2.B1 J2.B12 Q3.2 Q4.2 Q4.3 R2.1 R4.2 R11.2 R16.2 R18.2 R19.2 R25.1 S1.4 TP8.1 U1.2 U1.25 U2.49 U4.2 U5.2 U6.1 U6.2 U6.3 U6.6 U6.7 U7.2 U9.A2 U9.A6 U9.A7 U9.B4 U9.C1 U9.C6 U9.C7 X1.8 X1.13 | length 2931
  Top Layer w7: v1(-1081.46,166.95) -1077.79,166.95 -1067.81,176.93 R4.2 ; C9.2 v1(-1076.1,115.95) ; D4.1 -1069.8,446.73 -1053.62,462.91 v1(-1051.1,462.91) ; v1(-946.22,317.6) C13.2 ; v1(-927.59,398.37) R2.1 ; U4.2 -914.95,53.68 -888.05,53.68 -863.77,77.95 C7.2 v1(-841.1,115.95) ; U5.2 v1(-779.1,214.33) ; v1(-671.73,-118.9) -653.26,-137.36 U1.2 -575.95,-137.36 U1.25 ; v1(-625.32,-332.6) C18.2 ; v1(-530.59,357.2) X1.8 ; v1(-530.59,495) X1.13 ; v1(-370.55,-18.05) C2.2 -370.55,-72.33 -362.65,-80.23 -350.92,-80.23 -342.9,-88.26 -283.91,-88.26 U9.C1@-283.81,-88.37 ; C10.2 -283.59,-333.06 v1(-283.59,-296.92) U9.C7 U9.C6 U9.A6 ; U9.A7 U9.A6 ; U9.A2 -241.99,-117.68 -246.09,-121.78 U9.B4 -246.09,-235.79 U9.A6 ; v1(290.91,-72.4) 368.17,-72.4 379.41,-83.64 379.41,-227.4 ; C6.2 379.41,-227.4 ; v1(379.41,-244.9) 379.41,-227.4 ; U6.1 504.36,207.75 511.52,200.6 v1(524.05,200.6) ; v1@516.37,202.48 518.25,200.6 v1(524.05,200.6) ; U6.2 v1(524.05,200.6) ; U7.2 v1(528.89,480.83) ; U6.3 543.73,206.66 537.67,200.6 v1(524.05,200.6) ; C4.2 v1(594.32,627.84) ; U6.6 593.61,277.84 600.89,285.12 v1(600.89,297.53) ; U6.7 v1(600.89,297.53) ; C1.2 v1(587.28,407.83) ; v1@597.71,294.34 v1(600.89,297.53)
  Top Layer w12: J2.A1@-815.89,-144.44 J2.1@-815.89,-103.13 ; J2.1@-812.89,-442.13 J2.B1@-812.89,-400.13
  Bottom Layer w7: v1(-1011.1,592.83) -961.22,592.83 -938.94,570.55 -938.94,547.95 ; Q4.2 -938.94,547.95 ; Q4.3 -913.35,542.95 -918.35,547.95 -938.94,547.95 ; v1(-866.22,-301.97) R18.2 R16.2 ; J2.1@-846.09,-102.17 -846.09,-60.13 -836.51,-50.55 R11.2 ; R19.2 -726.6,627.95 v1(-696.1,627.95) ; Q3.2 v1(-661.1,507.84) ; C8.2 -370.55,33.55 v1(-370.55,-18.05) ; TP8.1@-312.53,467.83 TP8.1 -296.52,448.27 C14.2 ; v1(-241.1,480.83) C14.2 ; R25.1 v1(-208.81,46.75) ; C15.2 -196.1,452.95 -236.42,452.95 C14.2 ; v1@288.92,-70.42 v1(290.91,-72.4) ; C5.2 343.9,-226.89 361.91,-244.9 v1(379.41,-244.9)
  other v1: -1085.47,-431.62 388.91,-415.84 68.9,-222.01 -1085.47,-112.72 -1091.1,462.91 -1011.1,462.91 -1091.1,592.83 -1051.1,592.83
GREEN: R10.2 U2.29 | length 634.1
  Top Layer w7: U2.29 39.37,-386.18 v1(51.38,-398.19)
  Bottom Layer w7: v1(51.38,-398.19) 51.38,-444.13 75.51,-468.27 409.9,-468.27 442.85,-435.32 442.85,-359.17 424.84,-341.17 R10.2
INT1: U2.13 U6.4 | length 930.3
  Top Layer w7: U2.13 -71.92,-113.9 -75.22,-110.6 -75.22,16.27 -59.76,31.73 288.46,31.73 354.57,97.83 354.57,147.9 374.51,167.84 551.46,167.84 563.42,179.8 U6.4
INT2: R22.1 U2.11 U9.A3 | length 605.5
  Top Layer w7: U9.A3 -206.58,-145.19 -192.19,-145.19 -179.93,-132.93 -179.93,-63.59 -163.81,-47.46 v1(-163.81,-47.59) ; U2.11 -19.69,-54.69 v1(-5,-40)
  Bottom Layer w7: v1(-163.81,-47.59) -142.53,-47.59 -90,4.94 -90,80 -75.91,94.09 -16.52,94.09 -5,82.57 v1(-5,-40) ; v1@-163.81,-47.46 R22.1
IO0: Q1.6 R7.2 U2.23 | length 574.9
  Top Layer w7: Q1.6 v1(-398.98,-345) R7.2 ; v1(-83.36,-409.53) -83.36,-366.69 -90.02,-360.03 -90.02,-321.91 -78.86,-310.75 U2.23
  Bottom Layer w7: v1(-398.98,-345) -398.98,-322.83 -379.42,-303.27 -354.27,-303.27 -236.63,-420.91 -125.19,-420.91 -113.81,-409.53 v1(-83.36,-409.53)
LCD_BL: R20.1 U2.15 | length 1346
  Top Layer w7: v1(-689.32,577.83) -644.32,532.84 v1(-118.13,532.84) ; v1(-118.13,46.75) -93.81,22.43 -93.81,-133.59 -74.13,-153.27 U2.15
  Bottom Layer w7: R20.1 v1(-689.32,577.83) ; v1(-118.13,46.75) v1(-118.13,532.84)
LPn: R24.1 U2.12 U9.A5 | length 341.7
  Top Layer w7: U9.A5 -179.93,-206.26 -160,-186.33 -160,-163.63 -140.29,-143.92 -140.29,-124.98 v1(-125.91,-110.6) ; U2.12 v1(-39.37,-38.12)
  Bottom Layer w7: v1(-125.91,-110.6) -92.67,-77.36 R24.1 v1(-39.37,-38.12)
NetA1_1: C3.2 | length 145.2
  Top Layer w7: 418.91,-332.17 C3.2@418.91,-186.97
NetC3_1: C3.1 U2.2 | length 402.8
  Top Layer w7: U2.2 157.48,-47.37 161.58,-43.27 400.01,-43.27 418.24,-61.49 C3.1@418.24,-148.04
NetC7_1: C7.1 S1.1 U4.1 U4.3 | length 495.1
  Top Layer w7: C7.1@-848.82,15.12 C7.1
  Top Layer w10: U4.1 -953.78,15.12 -965.47,26.81 -965.47,79.92 -955.47,89.92 U4.3
  Top Layer w15: v1(-936.88,-183.12) -936.88,-38.12 -916.1,-17.34 U4.1 C7.1@-848.82,15.12
  Bottom Layer w15: S1.1 v1(-936.88,-183.12)
NetC19_1: C19.1 R17.1 U8.5 | length 917.5
  Top Layer w7: U8.5 -869.22,585.83 -862.22,592.83 -804.58,592.83 -794.32,582.57 -794.32,398.37 v1(-810.31,382.39)
  Bottom Layer w7: R17.1 C19.1 -1056.47,296.22 -1062.22,290.47 -1062.22,219.07 -1028.62,185.47 -850.89,185.47 -832.22,204.14 -832.22,360.47 v1(-810.31,382.39)
NetC19_2: C19.2 J1.2 Q4.6 Q4.7 U8.6 | length 904.5
  Top Layer w7: U8.6@-906.5,547.56 U8.6 v1(-906.22,587.83)
  Top Layer w12: J1.2 U8.6@-906.5,547.56
  Bottom Layer w7: C19.2 -1031.1,222.95 -1015.98,207.83 -938.94,207.83 ; Q4.7 -938.94,207.83 ; Q4.6 -913.35,207.83 ; v1(-906.22,587.83) -832.22,587.83 -805.46,561.07 -805.46,460.12 -856.22,409.36 -856.22,217.84 -866.22,207.83 -913.35,207.83 ; -938.94,207.83 -913.35,207.83
NetD1_1: D1.1 Q2.2 S1.2 | length 623.6
  Bottom Layer w7: Q2.2@-835.33,15.01 Q2.2 -812.22,9.45 -803.49,18.18 -803.49,34.2 -761.18,76.51 D1.1
  Bottom Layer w15: S1.2 -915.94,-242.17 -904.32,-230.55 -904.32,-152.34 -934.32,-122.34 -934.32,-16.98 -907.89,9.45 Q2.2
NetD2_1: D2.1 R14.1 | length 50.8
  Top Layer w7: D2.1 -1069.8,303.09 R14.1
NetD3_2: D3.2 R8.1 | length 93
  Top Layer w7: D3.2 v1(319.41,-413.27)
  Bottom Layer w7: v1@319.41,-411.65 v1(319.41,-413.27) ; v1@322.59,-410.09 v1(319.41,-413.27) ; R8.1 365.36,-380.78 365.36,-382.75 334.84,-413.27 v1(319.41,-413.27)
NetD3_3: D3.3 R10.1 | length 196.1
  Top Layer w7: v1(234.41,-418.27) 239.41,-413.27 D3.3
  Bottom Layer w7: v1(234.41,-418.27) 268.34,-418.27 345.44,-341.17 R10.1
NetD3_4: D3.4 R9.1 | length 184.8
  Top Layer w7: v1(239.41,-382.76) D3.4
  Bottom Layer w7: v1(239.41,-382.76) 274.79,-382.76 279.04,-378.5 354.38,-303.17 R9.1
NetD4_2: D4.2 R21.1 | length 51.3
  Top Layer w7: D4.2 R21.1
NetJ2_A5: J2.A5 R16.1 | length 95.1
  Top Layer w7: J2.A5 v1(-740.54,-223.23)
  Bottom Layer w7: R16.1 v1(-740.54,-223.23)
NetJ2_B5: J2.B5 R18.1 | length 94.1
  Top Layer w7: J2.B5 v1(-741.52,-341.34)
  Bottom Layer w7: R18.1 v1(-741.52,-341.34)
NetQ1_2: Q1.2 R3.1 | length 397.8
  Top Layer w7: Q1.2 -457.2,-392.28 -446.1,-381.18 -446.1,-352.91 -454.02,-345 -481.02,-345 -495.59,-330.43 -495.59,-302.92 -479.63,-286.97 -367.63,-286.97 -336.1,-318.5 R3.1
NetQ1_5: Q1.5 R6.1 | length 355.1
  Top Layer w7: v1(-542.16,-420.91) R6.1 ; Q1.5 -369.61,-392.28 -365.59,-388.27 v1(-365.59,-333.27) -362.32,-333.27 v1@-361.1,-334.49
  Bottom Layer w7: v1(-542.16,-420.91) -502.72,-381.46 -382.05,-381.46 -365.59,-365 v1(-365.59,-333.27)
NetQ3_1: Q3.1 R19.1 R20.2 | length 120
  Bottom Layer w7: Q3.1 R20.2 R19.1
NetQ3_3: Q3.3 R15.2 | length 73.7
  Bottom Layer w7: R15.2 Q3.3
NetQ4_1: Q4.1 Q4.8 | length 252.8
  Bottom Layer w7: Q4.8 -964.53,300.11 -971.53,307.11 -971.53,394.98 -964.53,401.98 Q4.1
NetQ4_4: Q4.4 U8.3 | length 104.8
  Top Layer w7: U8.3 v1(-832.22,485.47)
  Bottom Layer w7: Q4.4 -854.58,507.83 v1(-832.22,485.47)
NetQ4_5: Q4.5 U8.1 | length 231.1
  Top Layer w7: v1(-933.62,445.47) U8.1
  Bottom Layer w7: v1(-933.62,445.47) -887.76,399.61 Q4.5
NetR2_2: R2.2 U8.2 | length 47.1
  Top Layer w7: R2.2@-869.22,398.37 U8.2
NetR4_1: R4.1 U5.5 | length 61.5
  Top Layer w7: R4.1 U5.5
NetR5_2: R5.2 U6.12 | length 90.6
  Top Layer w7: R5.2@473.9,367.83 473.9,302.09 478.46,297.53 U6.12
NetR14_2: R14.2 U5.1 | length 243.3
  Top Layer w7: R14.2 -1030.43,225.56 -1024.28,219.41 -909.28,219.41 -899.32,209.45 -899.32,181.14 -895.11,176.93 U5.1
NetR15_1: R15.1 X1.11 | length 375.2
  Top Layer w7: v1(-684.32,382.39) -684.32,411.6 -655.4,440.52 -386.23,440.52 X1.11
  Bottom Layer w7: R15.1 -684.32,354.45 v1(-684.32,382.39)
NetR23_1: R23.1 U9.C2 | length 77.5
  Top Layer w7: R23.1 U9.C2
NetU1_5: U1.5 U1.6 | length 83.7
  Top Layer w7: U1.6 -652,-216.1 -656.1,-212 -656.1,-200.52 -652,-196.42 U1.5
RED: R8.2 U2.34 | length 470.6
  Top Layer w7: v1(118.11,-417.87) 137.8,-398.19 U2.34
  Bottom Layer w7: v1@119.41,-419.17 v1(118.11,-417.87) 118.11,-436.97 130.63,-449.49 398.24,-449.49 424.34,-423.39 424.34,-397.77 R8.2 ; R8.2@409.63,-377.06 R8.2@410.04,-377.47
RST: U2.39 X1.6 | length 1261.9
  Top Layer w7: X1.6 -254.84,302.09 -187.67,234.92 v1(184.41,234.92) ; U2.39 233.46,-291.06 254.41,-312.01 v1(254.41,-323.27)
  Bottom Layer w7: v1(184.41,234.92) 184.41,-253.27 v1(254.41,-323.27)
RTS: Q1.4 R3.2 U1.19 | length 575.3
  Top Layer w7: U1.19 -497.2,-73.27 -486.09,-62.17 -451.09,-62.17 -436.09,-77.17 -436.09,-187.51 -315.43,-308.17 -315.43,-351.79 -306.1,-361.12 -306.1,-413.77 -310.2,-417.87 R3.2 Q1.4
RXD: U1.21 U2.40 | length 1577.6
  Top Layer w7: U1.21 -536.57,-39.37 -430.57,66.63 -347.59,66.63 -280.85,133.37 29.53,133.37 41.17,121.73 225.55,121.73 v1(249.41,145.59) ; U2.40 242.52,-271.38 v1(294.41,-323.27)
  Bottom Layer w7: v1(249.41,145.59) 279.04,115.96 279.04,40.02 262.1,23.08 262.1,-85.97 314.41,-138.28 314.41,-240.67 274.41,-280.67 274.41,-303.27 v1(294.41,-323.27)
SCL: R13.1 TP5.1 U2.17 U6.13 U7.6 U9.C4 | length 1977.9
  Top Layer w7: v1(-335.43,-177.17) -335.22,-176.95 -283.81,-176.95 U9.C4 ; v1(-113.81,-178.37) -99.53,-192.64 U2.17 ; v1(-50,60) 6.63,60 10.72,55.91 280.64,55.91 329.57,104.84 v1@329.57,277.83 ; v1(329.45,284.87) 369.07,284.87 376.1,277.84 U6.13 ; v1(329.57,574.85) U7.6
  Bottom Layer w7: v1(-335.43,-177.17) -334.23,-178.37 -163.81,-178.37 ; v1(-113.81,-178.37) -163.81,-178.37 ; v1@-48.92,58.92 v1(-50,60) -50,9.83 -163.81,-103.97 -163.81,-178.37 ; v1(329.45,284.87) v1@329.57,284.87 ; v1@329.57,277.83 v1@329.57,284.87 ; v1(329.57,574.85) v1@329.57,284.87 ; TP5.1 398.91,285.18 R13.1 v1@329.57,284.87
SDA: R12.1 TP6.1 U2.20 U6.14 U7.1 U9.C3 | length 2320.7
  Top Layer w7: v1(-315.43,-147.2) U9.C3 ; v1(-245.59,75.73) -231.4,89.92 7.86,89.92 22.05,75.73 264.41,75.73 294.92,106.24 294.92,242.83 294.92,433.19 312.56,450.83 U7.1 ; v1(-162,-392) -152.01,-382.01 -152.01,-304.01 -99.69,-251.69 U2.20 ; v1(359.57,242.83) 360.48,242.83 375.8,258.16 U6.14
  Bottom Layer w7: v1(-245.59,75.73) -245.59,-77.36 v1(-315.43,-147.2) -354.53,-147.2 -365.59,-158.27 -365.59,-254.2 -227.79,-392 v1(-162,-392) ; v1(294.41,242.83) v1(359.57,242.83) R12.1 398.91,242.4 TP6.1
SPI_CLK: U2.35 X1.4 | length 1172.8
  Top Layer w7: X1.4 -271.21,246.97 -204.04,179.8 v1@49.04,179.8 ; v1(157.48,-417.87) U2.35
  Bottom Layer w7: v1(49.04,180.36) 49.04,24.8 90,-16.16 90,-143.27 118.11,-171.38 118.11,-378.5 v1(157.48,-417.87)
SPI_MOSI: U2.36 X1.3 | length 1187.2
  Top Layer w7: X1.3 -275.51,219.41 -208.35,152.24 v1(84.04,152.24) ; U2.36 177.17,-401.14 v1(193.9,-417.87)
  Bottom Layer w7: v1(84.04,152.24) 84.04,54.51 157.48,-18.93 157.48,-381.46 v1(193.9,-417.87)
TFT_CS: U2.24 X1.7 | length 1207.3
  Top Layer w7: X1.7 v1(-13.81,329.65) ; U2.24 -60.38,-331.16 -60.38,-380.83 v1(-48.92,-392.28)
  Bottom Layer w7: v1(-48.92,-392.28) -48.92,-350.37 7.68,-293.77 7.68,-130.59 25,-113.27 25,106.78 -13.81,145.59 v1(-13.81,329.65)
TOUCH_1: TP1.1 U2.16 | length 1042.5
  Top Layer w7: TP1.1 -741.52,-502.17 -694.02,-454.67 -294.63,-454.67 -187.09,-347.13 -187.09,-240.23 -140.81,-193.94 -140.81,-168.81 -124,-152 -100.17,-152 -79.22,-172.95 U2.16
TOUCH_2: TP2.1 U2.18 | length 585.5
  Top Layer w7: TP2.1 -310.1,-502.17 -170.09,-362.16 -170.09,-249.09 -133.32,-212.32 U2.18
TOUCH_3: TP3.1 U2.21 | length 404.3
  Top Layer w7: U2.21 -92.38,-271.38 -134,-313 -134,-443.92 -156.11,-466.03 -156.11,-498.06 -152.01,-502.17 TP3.1
TOUCH_4: TP4.1 U2.22 | length 677.3
  Top Layer w7: U2.22 -84.06,-291.06 -114,-321 -114,-419.27 -96.27,-437 81.79,-437 146.95,-502.17 TP4.1
TXD: U1.20 U2.41 | length 1337.6
  Top Layer w7: U1.20 -516.89,-52.3 -417.83,46.75 -339.57,46.75 -272.64,113.68 17.56,113.68 29.51,101.73 v1(249.41,101.73) ; U2.41 197.68,-251.93 265.67,-251.93 v1(265.91,-252.17)
  Bottom Layer w7: v1(249.41,101.73) 249.41,50.91 239.41,40.91 239.41,-95.44 289.41,-145.44 289.41,-230.59 267.83,-252.17 v1(265.91,-252.17)
VBAT: C13.1 J1.1 Q2.3 R17.2 U5.3 | length 1143.5
  Top Layer w7: J1.1 -965.47,430.42 -953.79,418.74 -953.79,398.37 -953.79,377.38 -936.89,360.47 -855.2,360.47 -851.1,356.37 C13.1
  Top Layer w12: U5.3 C13.1 -849.76,318.94 v1(-804.83,318.94)
  Bottom Layer w7: R17.2 -1073.56,382.39 -1085.47,370.47 -1085.47,212.32 -1033.62,160.47 -804.83,160.47 ; v1(-804.83,318.94) -804.83,160.47 ; Q2.3 -804.83,95.43 -804.83,160.47
VL_RST: R25.2 U9.A1 | length 70.3
  Top Layer w7: U9.A1 v1(-208.59,-47.71) v1@-208.59,-47.59
  Bottom Layer w7: R25.2 -208.59,-18.27 v1(-208.59,-47.71)
VUSB: C18.1 D1.2 D2.2 J2.A4 J2.A9 J2.B4 J2.B9 Q2.1 R11.1 R21.2 U1.7 U1.8 U5.4 | length 2038.3
  Top Layer w7: R21.2 -981.1,303.46 ; U5.4 -955.43,251.73 -981.1,277.4 -981.1,303.46 ; J2.B4@-795.89,-368.44 -683.01,-368.44 -669.32,-354.75 -669.32,-310.55 -655.93,-297.17 C18.1 -595.63,-269.67 ; J2.B4 -875.51,-363.14 -895.11,-343.54 -895.11,-203.54 -873.4,-181.84 J2.B9 ; v1(-731.05,-50.55) -731.05,88.45 -784.24,141.64 -1091.95,141.64 -1106.77,156.47 -1106.77,326.49 -1090.43,342.83 -1040.43,342.83 -1032.77,335.17 D2.2 -981.1,303.46 ; U1.7 -595.63,-269.67 ; U1.8 -575.95,-265.57 -580.05,-269.67 -595.63,-269.67
  Top Layer w20: J2.A4@-794.32,-175.55 -750.03,-175.55 -731.05,-156.57 v1(-731.05,-50.55)
  Bottom Layer w7: D1.2@-680.38,-50.55 D1.2
  Bottom Layer w12: Q2.1 R11.1 v1(-731.05,-50.55) D1.2@-680.38,-50.55
pads on no net: J2. J2.A8 J2.B8 S1.3 U1.1 U1.9 U1.10 U1.11 U1.12 U1.13 U1.14 U1.15 U1.16 U1.17 U1.18 U1.22 U1.24 U2.5 U2.6 U2.7 U2.8 U2.10 U2.14 U2.25 U2.26 U2.27 U2.30 U2.31 U2.32 U2.33 U2.38 U2.44 U2.45 U2.47 U2.48 U4.4 U6.9 U6.10 U6.11 U7.3 U7.4 U8.4 U9.C5 X1.1 X1.2 X1.9

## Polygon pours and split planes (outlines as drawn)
GND on Layer 1 (GND) (split plane): 583.46,662.53 587.95,661.64 592.28,660.17 596.39,658.14 600.19,655.6 603.63,652.58 606.65,649.14 609.19,645.34 611.22,641.23 612.69,636.9 613.58,632.41 613.85,628.28 613.85,628.26 613.86,628.2 613.83,627.93 613.82,627.84 613.81,627.84 613.85,628.26 612.75,628.3 612.56,627.84 613.81,627.84 613.82,627.78 613.81,627.7 613.81,167.83 400.01,167.83 400.01,-512.16 607.53,-512.16 606.66,-513.47 603.64,-516.91 600.2,-519.92 596.4,-522.47 592.29,-524.49 587.96,-525.96 583.47,-526.86 579.12,-527.14 578.66,-527.1 578.52,-527.08 578.45,-527.09 578.4,-527.08 578.4,-525.84 578.03,-525.99 578.05,-527.08 -1070.55,-527.08 -1070.56,-527.08 -1070.58,-527.08 -1070.68,-527.09 -1070.79,-527.08 -1070.81,-527.08 -1071.34,-527.14 -1075.67,-526.86 -1080.16,-525.97 -1084.49,-524.49 -1088.6,-522.47 -1092.4,-519.93 -1095.84,-516.91 -1098.86,-513.47 -1101.4,-509.66 -1103.43,-505.56 -1104.9,-501.22 -1105.71,-497.17 -1104.76,-497.17 -1106.01,-494.16 -1106.01,-493.37 -1106.02,-493.26 -1105.25,-493.32 -1104.77,-492.17 -1106.02,-492.17 -1106.06,-492.6 -1106.07,-492.47 -1106.04,-492.17 -1106.02,-492.17 -1106.03,-492.05 -1106.01,-491.81 -1106.01,-491.8 -1106.02,627.37 -1104.98,627.34 -1104.78,627.83 -1106.02,627.83 -1106.03,627.9 -1106.02,627.98 -1106.06,628.36 -1105.79,632.4 -1104.9,636.89 -1103.43,641.22 -1101.4,645.33 -1098.86,649.13 -1095.84,652.57 -1092.4,655.59 -1088.6,658.13 -1084.49,660.16 -1080.16,661.63 -1075.67,662.52 -1071.36,662.81 -1070.79,662.75 -1070.68,662.76 -1070.6,662.75 -1070.6,661.51 -1070,661.76 -1070.04,662.75 578.23,662.75 578.3,662.76 578.34,662.76 578.54,662.78 578.88,662.82 578.88,662.81 579.02,662.82
+3.3V on Layer 2 (PWR) (split plane): 583.46,662.53 587.95,661.64 592.28,660.17 596.39,658.14 600.19,655.6 603.63,652.58 606.65,649.14 609.19,645.34 611.22,641.23 612.69,636.9 613.58,632.41 613.85,628.28 613.85,628.26 613.86,628.2 613.83,627.93 613.82,627.84 613.81,627.84 613.85,628.26 612.75,628.3 612.56,627.84 613.81,627.84 613.82,627.78 613.81,627.7 613.81,167.84 400.01,167.84 400.01,-502.16 612.38,-502.16 611.23,-505.56 609.2,-509.66 606.66,-513.47 603.64,-516.91 600.2,-519.92 596.4,-522.47 592.29,-524.49 587.96,-525.96 583.47,-526.86 579.12,-527.14 578.66,-527.1 578.52,-527.08 578.45,-527.09 578.4,-527.08 578.4,-525.84 578.03,-525.99 578.05,-527.08 -1070.55,-527.08 -1070.56,-527.08 -1070.58,-527.08 -1070.68,-527.09 -1070.79,-527.08 -1070.81,-527.08 -1071.34,-527.14 -1075.67,-526.86 -1080.16,-525.97 -1084.49,-524.49 -1088.6,-522.47 -1092.4,-519.93 -1095.84,-516.91 -1098.86,-513.47 -1101.4,-509.66 -1103.43,-505.56 -1104.9,-501.22 -1105.71,-497.17 -1104.76,-497.17 -1106.01,-494.16 -1106.01,-493.37 -1106.02,-493.26 -1105.25,-493.32 -1104.77,-492.17 -1106.02,-492.17 -1106.06,-492.6 -1106.07,-492.47 -1106.04,-492.17 -1106.02,-492.17 -1106.03,-492.05 -1106.01,-491.81 -1106.01,-491.8 -1106.02,627.37 -1104.98,627.34 -1104.78,627.83 -1106.02,627.83 -1106.03,627.9 -1106.02,627.98 -1106.06,628.36 -1105.79,632.4 -1104.9,636.89 -1103.43,641.22 -1101.4,645.33 -1098.86,649.13 -1095.84,652.57 -1092.4,655.59 -1088.6,658.13 -1084.49,660.16 -1080.16,661.63 -1075.67,662.52 -1071.36,662.81 -1070.79,662.75 -1070.68,662.76 -1070.6,662.75 -1070.6,661.51 -1070,661.76 -1070.04,662.75 578.23,662.75 578.3,662.76 578.34,662.76 578.54,662.78 578.88,662.82 578.88,662.81 579.02,662.82

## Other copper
Top Layer:
  rectangle net GND: 374.51,-433.56 418.24,-398.13
  text "1" at 573.91,-492.17 h40
Bottom Layer:
  text "4" at 588.91,-492.17 h40
Layer 1 (GND) (plane layer: these items are gaps in the copper):
  pour cut-out: 400.01,167.83 400.01,-512.16 628.9,-512.16 628.9,167.83
  text "2" at 529.78,-444.11 h40
Layer 2 (PWR) (plane layer: these items are gaps in the copper):
  pour cut-out: 400.01,167.84 400.01,-502.16 628.4,-502.16 628.39,167.84
  lines w10: 417.41,-63.27 426.41,-54.27
  text "3" at 529.46,-445.95 h40

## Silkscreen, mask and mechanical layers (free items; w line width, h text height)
Top Overlay:
  lines w7: -1101.61,288.94 -1101.61,318.94 ; -1101.1,377.83 -1101.1,407.83
Bottom Overlay:
  drawing of 540 lines, arcs and shapes, not listed
  text "Rev1" at -380.59,271.83 h35
  text "ESP32 Sensor Board" at 100,-190 h35
Mechanical 1:
  lines w10: -1121.09,-497.17 -1121.1,627.83 cw(c-1071.1,627.83) -1070.6,677.83 578.39,677.83 cw(c578.89,627.84) 628.89,627.84 628.9,-492.17 cw(c578.9,-492.17) 578.4,-542.16 -1070.6,-542.17 cw(c-1071.1,-492.17) -1121.1,-492.17
Top_Assembly:
  lines w2: 308.54,-423.79 308.54,-372.17 253.91,-372.17 253.91,-424.17 308.91,-424.17 ; -289.09,-328.5 -289.09,-179.17 -203.09,-179.17 -203.09,-328.5 -289.09,-328.5
Bottom_Assembly:
  lines w2: -973.09,294.83 -973.09,476.73 -879.09,476.73 -879.09,294.83 -973.09,294.83

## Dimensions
-1070.6,677.84 to -1070.6,-542.17 on Drill Drawing
-1121.1,492.83 to 628.89,627.84 on Drill Drawing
